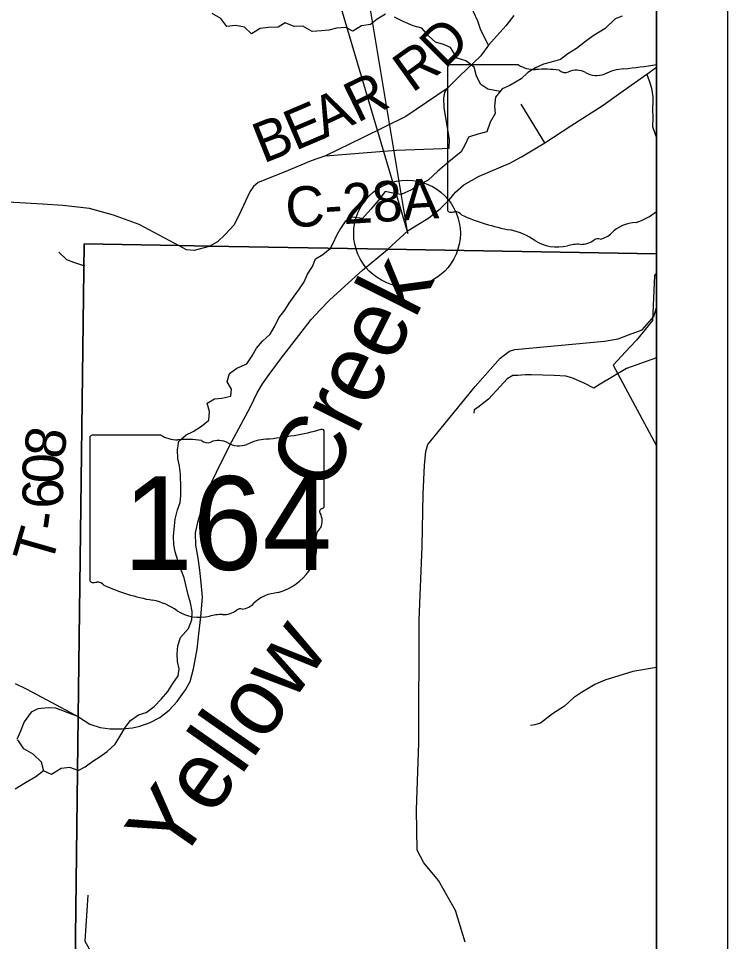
# Model space of a CAD drawing. Extents: x -20.5 to 34, y -66 to 23.9.
# Drawn here: x 8.003 to 9, y 16.344 to 17.643 of the extents above; entities that cross this region are included whole.
import ezdxf

# ---------------------------------------------------------------- set-up
doc = ezdxf.new("R2010")
doc.units = 0
for name, color, linetype in [('Default', 7, 'Continuous'), ('GM_X_County_Road_Text', 7, 'Continuous'), ('GM_X_County_Text', 7, 'Continuous'), ('GM_X_Minor_River_Text', 7, 'Continuous'), ('GM_X_Section_Text', 7, 'Continuous'), ('GM_X_State_Route', 7, 'Continuous'), ('GM_X_State_Shield', 7, 'Continuous'), ('GM_X_Township_Road', 7, 'Continuous'), ('GM_X_Township_Road_Text', 7, 'Continuous'), ('GM_X_Unincorporated', 7, 'Continuous'), ('GM_X_Unincorporated_Location', 7, 'Continuous'), ('SH_Cut_Line', 7, 'Continuous'), ('SH_Data', 7, 'Continuous'), ('SH_Text', 7, 'Continuous')]:
    doc.layers.add(name, color=color, linetype=linetype)

msp = doc.modelspace()

# ---------------------------------------------------------------- linework, layer by layer
at = {"layer": 'Default'}
for points in [[(2.1, 20.9), (8.9, 20.9), (8.9, 14.1), (2.1, 14.1)], [(8.9, 14.3068), (8.9, 17.3115), (8.5216, 17.3182), (8.271, 17.3227), (8.2289, 17.3235), (8.0955, 17.3258), (8.087, 16.6605), (8.0825, 16.3121), (8.0784, 15.8902), (8.0662, 14.9881), (8.0605, 14.6038), (8.0589, 14.5033), (8.0585, 14.4588), (8.0565, 14.3169), (8.8167, 14.3089)], [(8.9, 17.0415), (8.9, 17.285), (8.8972, 17.2813), (8.8943, 17.2178), (8.8719, 17.1901), (8.8625, 17.1804), (8.8391, 17.1549)]]:
    msp.add_lwpolyline(points, close=True, dxfattribs=at)
msp.add_lwpolyline([(8.0662, 14.9881), (8.0784, 15.8902), (8.0825, 16.3121), (8.087, 16.6605), (8.0955, 17.3258), (8.2289, 17.3235), (8.271, 17.3227), (8.5216, 17.3182), (8.9, 17.3115), (8.9, 18.8361), (8.7292, 18.8379), (8.3774, 18.8452)], dxfattribs=at)
at = {"layer": 'GM_X_County_Text'}
msp.add_line((8.7431, 17.4678), (8.7098, 17.5223), dxfattribs=at)
for points in [[(8.664, 17.6053), (8.6581, 17.616), (8.6526, 17.6277), (8.6487, 17.6393), (8.6426, 17.6523), (8.6394, 17.6621), (8.6374, 17.6671), (8.6406, 17.671)], [(8.8865, 17.5646), (8.8911, 17.5508), (8.8931, 17.5448), (8.8942, 17.5388), (8.8948, 17.5333), (8.895, 17.5252), (8.8943, 17.5162), (8.895, 17.5027), (8.8945, 17.4909), (8.8985, 17.4785), (8.9, 17.4753)], [(8.6086, 17.4603), (8.6091, 17.4726), (8.6014, 17.5172), (8.6012, 17.5308), (8.6026, 17.5386), (8.6056, 17.5444)]]:
    msp.add_lwpolyline(points, dxfattribs=at)
at = {"layer": 'GM_X_Minor_River_Text'}
for points in [[(8.5191, 17.649), (8.5075, 17.642), (8.4978, 17.6343), (8.4853, 17.6326), (8.473, 17.6252), (8.4634, 17.6304), (8.4502, 17.6294), (8.4393, 17.6266), (8.4291, 17.6257), (8.4158, 17.6247), (8.4028, 17.6321), (8.3907, 17.6316), (8.3778, 17.6367), (8.3681, 17.6308), (8.3544, 17.6303), (8.3427, 17.6286), (8.3304, 17.6212), (8.3208, 17.6305), (8.3082, 17.633), (8.2958, 17.6317), (8.2876, 17.6429), (8.2754, 17.6499)], [(8.8518, 17.646), (8.842, 17.6425), (8.8279, 17.6286), (8.811, 17.6185), (8.8001, 17.6104), (8.7874, 17.6007), (8.7754, 17.5933), (8.7653, 17.5852), (8.7518, 17.5816), (8.7412, 17.5784), (8.7299, 17.5737), (8.7194, 17.5667), (8.7097, 17.5582), (8.694, 17.5488), (8.6831, 17.5438), (8.6738, 17.5322), (8.6725, 17.5193), (8.6734, 17.5091), (8.6664, 17.4968), (8.6617, 17.4835), (8.6489, 17.4803), (8.6357, 17.4759), (8.6309, 17.4656), (8.6254, 17.4553), (8.6082, 17.441), (8.5925, 17.4282), (8.5791, 17.4155), (8.5656, 17.4085), (8.5558, 17.4019), (8.5412, 17.3952), (8.5317, 17.3966), (8.5188, 17.3994), (8.5095, 17.3879), (8.4983, 17.3745), (8.4868, 17.3614), (8.472, 17.3631), (8.4623, 17.3572), (8.456, 17.3473), (8.4501, 17.3373), (8.445, 17.3262), (8.4412, 17.3194)], [(8.6803, 17.5403), (8.663, 17.5435), (8.6531, 17.5501), (8.6472, 17.5618), (8.6436, 17.5746), (8.6321, 17.5832), (8.6196, 17.5872), (8.6103, 17.6022), (8.6004, 17.6062), (8.5894, 17.6095), (8.5794, 17.6184), (8.5701, 17.6293), (8.558, 17.6325), (8.5439, 17.6388), (8.5317, 17.645)], [(8.0871, 16.5848), (8.0968, 16.5899), (8.1077, 16.5978), (8.1178, 16.6042), (8.1275, 16.6113), (8.1387, 16.6215), (8.1456, 16.6323), (8.1528, 16.6451), (8.1606, 16.6552), (8.1718, 16.6632), (8.1823, 16.6661), (8.1939, 16.6748), (8.2043, 16.6854), (8.2131, 16.6959), (8.22, 16.7072), (8.2273, 16.718), (8.2289, 16.7276), (8.2267, 16.7382), (8.226, 16.7488), (8.2272, 16.7603), (8.2307, 16.7718), (8.2422, 16.7843), (8.2468, 16.7966), (8.2472, 16.8084), (8.2449, 16.8205), (8.2416, 16.8318), (8.2359, 16.856), (8.231, 16.8692), (8.2273, 16.8789), (8.2234, 16.8925), (8.2213, 16.9024), (8.2209, 16.9145), (8.2218, 16.9241), (8.2233, 16.9382), (8.2267, 16.9516), (8.2302, 16.9616), (8.2311, 16.9715), (8.2312, 16.9818), (8.2306, 17.0015), (8.2295, 17.0129), (8.2269, 17.0235), (8.2266, 17.036), (8.2285, 17.0482), (8.2389, 17.0569), (8.2487, 17.0618), (8.2603, 17.0693), (8.2707, 17.0776), (8.2715, 17.0898), (8.2685, 17.1015), (8.2786, 17.1079), (8.2888, 17.1086), (8.3017, 17.1116), (8.3026, 17.1215), (8.2962, 17.1316), (8.2996, 17.1435), (8.3101, 17.151), (8.324, 17.1568), (8.3317, 17.1684), (8.3378, 17.1792), (8.3463, 17.189), (8.3571, 17.1988), (8.3636, 17.2097), (8.369, 17.2216), (8.3775, 17.2325), (8.3836, 17.2422), (8.3906, 17.2523), (8.3979, 17.2624), (8.4049, 17.2725), (8.4095, 17.2829), (8.4164, 17.2941), (8.4207, 17.3045), (8.4309, 17.3107), (8.4412, 17.3194)], [(8.0962, 17.2944), (8.081, 17.2996), (8.0711, 17.3032), (8.0599, 17.314)], [(8.9, 17.1656), (8.8581, 17.1502), (8.8209, 17.1281), (8.8119, 17.1226), (8.7985, 17.1299), (8.7809, 17.1371), (8.7728, 17.1396), (8.7561, 17.1404), (8.7242, 17.1416), (8.7158, 17.1414), (8.7102, 17.1409), (8.7052, 17.1404), (8.698, 17.1403), (8.6901, 17.1359), (8.6805, 17.1251), (8.6637, 17.1073), (8.6491, 17.0956), (8.6439, 17.0924), (8.6432, 17.0875)], [(8.9, 16.7294), (8.8668, 16.7238), (8.8276, 16.7119), (8.8133, 16.7056), (8.7945, 16.6942), (8.7833, 16.6867), (8.7706, 16.675), (8.7541, 16.6644), (8.7372, 16.6512), (8.7289, 16.6487), (8.7229, 16.6482)], [(8.0386, 16.5839), (8.0352, 16.5962), (8.0237, 16.6078), (8.0107, 16.6152), (8.0022, 16.6276)], [(8.0871, 16.5848), (8.0751, 16.5889), (8.063, 16.5876), (8.0495, 16.579), (8.0381, 16.5841), (8.0272, 16.5756), (8.013, 16.5675), (7.9983, 16.5585)], [(8.1003, 16.409), (8.0961, 16.3444), (8.1036, 16.3313)]]:
    msp.add_lwpolyline(points, dxfattribs=at)
at = {"layer": 'GM_X_State_Route'}
msp.add_line((8.5987, 17.4601), (8.6086, 17.4603), dxfattribs=at)
for points in [[(8.6994, 17.6472), (8.6882, 17.6326), (8.664, 17.6053), (8.6531, 17.5904), (8.6231, 17.5619), (8.6056, 17.5444), (8.5477, 17.5051), (8.4866, 17.4748), (8.4345, 17.4496), (8.4147, 17.4424), (8.3764, 17.4266), (8.3399, 17.4123), (8.3334, 17.4065), (8.3285, 17.399), (8.3163, 17.3729), (8.3062, 17.3524), (8.2937, 17.3388), (8.2829, 17.3288), (8.2712, 17.3222), (8.25, 17.3162), (8.2392, 17.3173), (8.2291, 17.323), (8.1728, 17.3531), (8.1366, 17.3663), (8.1026, 17.3757), (8.0654, 17.3799), (8.0367, 17.3815), (8.0049, 17.3833), (7.9794, 17.3849)], [(8.4345, 17.4496), (8.5344, 17.4574), (8.5987, 17.4601)], [(8.6311, 16.3432), (8.6177, 16.3874), (8.5934, 16.4298), (8.5728, 16.4548), (8.5637, 16.4725), (8.5626, 16.5291), (8.566, 16.6237), (8.5664, 16.7968), (8.5707, 16.8998), (8.5719, 16.9742), (8.5741, 17.0137), (8.5756, 17.0335), (8.5784, 17.0434), (8.645, 17.1252), (8.6805, 17.165), (8.6932, 17.1748), (8.7011, 17.1772), (8.827, 17.1888), (8.8463, 17.1922), (8.8609, 17.1978), (8.8798, 17.2048), (8.8964, 17.2235), (8.9, 17.2362)], [(8.0872, 16.66), (8.0554, 16.6725), (8.0446, 16.6726), (8.0303, 16.6712), (8.0206, 16.6669), (8.011, 16.653), (8.006, 16.64), (8.0007, 16.6282)]]:
    msp.add_lwpolyline(points, dxfattribs=at)
at = {"layer": 'GM_X_State_Shield'}
for p, q in [((8.7062, 17.5775), (8.6096, 17.5775)), ((8.9, 17.3712), (8.9, 17.5784)), ((8.6064, 17.574), (8.6064, 17.3739))]:
    msp.add_line(p, q, dxfattribs=at)
for centre, major_axis, start_param, end_param in [((8.6102, 17.5745), (0.00382, 0), 1.727492, 3.291633), ((8.7291, 17.6007), (0.037, 0), 4.042888, 4.731792), ((8.8186, 17.8503), (0.3495, 0), 4.814394, 4.947512), ((8.7414, 17.4651), (0.133, 0), 1.404758, 1.657859), ((8.7716, 17.5755), (0.0107, 0), 3.836095, 5.185415), ((8.7873, 17.5524), (0.0222, 0), 0.950623, 2.079405), ((8.816, 17.5841), (0.0267, 0), 4.08156, 5.145723), ((8.8632, 17.5164), (0.0703, 0), 1.699012, 2.107814), ((8.6102, 17.3735), (0.00385, 0), 2.993084, 4.5083), ((8.6108, 17.394), (0.0294, 0), 4.665946, 4.897461), ((8.6168, 17.3624), (0.0106, 0), 0.519207, 1.627899), ((8.8382, 17.4206), (0.0874, 0), 5.101753, 5.498241), ((8.7506, 17.5422), (0.2524, 0), 4.195997, 4.488961), ((8.875, 17.3177), (0.0479, 0), 1.647645, 2.488434), ((8.6754, 17.284), (0.079, 0), 0.823519, 1.323587), ((8.7608, 17.3614), (0.0501, 0), 4.026481, 4.996735), ((8.7934, 17.3464), (0.0267, 0), 4.691044, 5.507374), ((8.8176, 17.327), (0.00752, 0), 1.147584, 2.315152), ((8.8144, 17.3545), (0.0282, 0), 4.937069, 5.64225), ((8.7897, 17.2922), (0.0412, 0), 1.495662, 1.94098)]:
    msp.add_ellipse(centre, major_axis=major_axis, ratio=0.8, start_param=start_param, end_param=end_param, dxfattribs=at)
at = {"layer": 'GM_X_Township_Road'}
for points in [[(8.5218, 17.3176), (8.5511, 17.3444), (8.5801, 17.3626), (8.5961, 17.3752), (8.6089, 17.3883), (8.6176, 17.3986), (8.6294, 17.409), (8.6508, 17.4211), (8.6939, 17.4391), (8.7103, 17.4481), (8.7431, 17.4678), (8.7797, 17.4917), (8.8251, 17.521), (8.8466, 17.5362), (8.8645, 17.5489), (8.8865, 17.5646), (8.9, 17.5742)], [(8.2568, 16.777), (8.2596, 16.8007), (8.2615, 16.8284), (8.26, 16.8489), (8.2582, 16.8667), (8.2557, 16.8834), (8.2524, 16.9019), (8.2518, 16.9186), (8.255, 16.9342), (8.2633, 16.9609), (8.275, 16.9907), (8.2879, 17.0182), (8.303, 17.0476), (8.3196, 17.0779), (8.3292, 17.0966), (8.3384, 17.1161), (8.3462, 17.1287), (8.3555, 17.1421), (8.373, 17.1652), (8.3972, 17.197), (8.4147, 17.2193), (8.4274, 17.2327), (8.4405, 17.2466), (8.4618, 17.2662), (8.4869, 17.2886), (8.5218, 17.3176)], [(8.0872, 16.66), (8.1032, 16.65), (8.1177, 16.6453), (8.1318, 16.6432), (8.1485, 16.6431), (8.1632, 16.6448), (8.1738, 16.6468), (8.1882, 16.652), (8.2017, 16.6594), (8.2148, 16.6694), (8.226, 16.6817), (8.2379, 16.6982), (8.2442, 16.7097), (8.2493, 16.7276), (8.2542, 16.7554), (8.2568, 16.777)], [(7.9984, 16.7071), (8.0139, 16.6994), (8.0498, 16.6802), (8.0872, 16.66)]]:
    msp.add_lwpolyline(points, dxfattribs=at)
at = {"layer": 'GM_X_Unincorporated'}
for p, q in [((8.2031, 17.0564), (8.1066, 17.0564)), ((8.4329, 16.9567), (8.4329, 17.0614)), ((8.1034, 17.053), (8.1034, 16.8529)), ((8.4329, 16.9567), (8.4329, 16.9567))]:
    msp.add_line(p, q, dxfattribs=at)
for centre, major_axis, start_param, end_param in [((8.1071, 17.0534), (0.00382, 0), 1.712693, 3.28349), ((8.2261, 17.0797), (0.037, 0), 4.042523, 4.731795), ((8.3155, 17.3293), (0.3495, 0), 4.814394, 5.042369), ((8.4293, 17.0618), (0.00367, 0), 6.141152, 7.989035), ((8.2384, 16.9441), (0.133, 0), 1.404758, 1.657858), ((8.2686, 17.0544), (0.0107, 0), 3.836095, 5.185415), ((8.2843, 17.0313), (0.0222, 0), 0.950623, 2.079405), ((8.3129, 17.063), (0.0267, 0), 4.081561, 5.145723), ((8.3601, 16.9953), (0.0703, 0), 1.699011, 2.107814), ((8.4321, 16.949), (0.00568, 0), 1.883978, 3.671073), ((8.429, 16.9563), (0.00393, 0), 5.05454, 6.418171), ((8.396, 16.9358), (0.0341, 0), 5.934695, 6.695948), ((8.4461, 16.9129), (0.0248, 0), 2.387724, 3.262537), ((8.3351, 16.8996), (0.0874, 0), 5.101752, 6.440018), ((8.1072, 16.8524), (0.00385, 0), 3.00124, 4.508301), ((8.1078, 16.8729), (0.0294, 0), 4.665946, 4.897461), ((8.1138, 16.8413), (0.0106, 0), 0.519207, 1.627899), ((8.2476, 17.0211), (0.2524, 0), 4.195997, 4.488961), ((8.1723, 16.763), (0.079, 0), 0.823519, 1.323587), ((8.372, 16.7967), (0.0479, 0), 1.647645, 2.488434), ((8.2578, 16.8403), (0.0501, 0), 4.026481, 4.996735), ((8.2904, 16.8253), (0.0267, 0), 4.691044, 5.507374), ((8.3145, 16.806), (0.00752, 0), 1.147584, 2.315152), ((8.3113, 16.8335), (0.0282, 0), 4.937069, 5.64225), ((8.2867, 16.7711), (0.0412, 0), 1.495662, 1.94098)]:
    msp.add_ellipse(centre, major_axis=major_axis, ratio=0.8, start_param=start_param, end_param=end_param, dxfattribs=at)
at = {"layer": 'SH_Cut_Line'}
msp.add_lwpolyline([(8.0662, 14.9881), (8.0784, 15.8902), (8.0825, 16.3121), (8.087, 16.6605), (8.0955, 17.3258), (8.2289, 17.3235), (8.271, 17.3227), (8.5216, 17.3182), (8.9, 17.3115), (8.9, 20.9), (2.1, 20.9), (2.1, 14.4131)], dxfattribs=at)
msp.add_lwpolyline([(8.9, 14.3068), (8.9, 17.3115), (8.5216, 17.3182), (8.271, 17.3227), (8.2289, 17.3235), (8.0955, 17.3258), (8.087, 16.6605), (8.0825, 16.3121), (8.0784, 15.8902), (8.0662, 14.9881), (8.0605, 14.6038), (8.0589, 14.5033), (8.0585, 14.4588), (8.0565, 14.3169), (8.8167, 14.3089)], close=True, dxfattribs=at)
at = {"layer": 'SH_Data'}
for p, q in [((9, 21), (9, 14)), ((8.9, 20.9), (8.9, 14.1))]:
    msp.add_line(p, q, dxfattribs=at)
at = {"layer": 'SH_Text'}
msp.add_lwpolyline([(8.5505, 17.3404), (8.3774, 18.3792), (8.2428, 18.3792)], close=True, dxfattribs=at)
msp.add_circle((8.5493, 17.3404), 0.075, dxfattribs=at)

# ---------------------------------------------------------------- texts
at = {"layer": 'GM_X_County_Road_Text'}
for s, height, rotation, p in [('Creek', 0.09469, 63.2958, (8.4368, 16.9733)), ('Yellow', 0.09471, 54.983, (8.2266, 16.4491))]:
    msp.add_text(s, height=height, rotation=rotation, dxfattribs=at).set_placement(p)
at = {"layer": 'GM_X_Section_Text'}
for s, rotation, p in [('8', 80.8384, (8.0658, 17.0212)), ('0', 88.5635, (8.0651, 16.9882)), ('6', 91.7241, (8.0662, 16.9541)), ('-', 82.1938, (8.0625, 16.9207)), ('T', 73.9781, (8.0489, 16.8711))]:
    msp.add_text(s, height=0.0568, rotation=rotation, dxfattribs=at).set_placement(p)
at = {"layer": 'GM_X_Township_Road_Text'}
for s, height, rotation, p in [('D', 0.0568, 44.8007, (8.6019, 17.5709)), ('R', 0.0568, 35.6146, (8.5565, 17.5374)), ('R', 0.0568, 25.9888, (8.4792, 17.4956)), ('A', 0.0568, 25.2482, (8.4332, 17.474)), ('E', 0.0568, 23.0721, (8.392, 17.4563)), ('B', 0.0568, 21.6666, (8.3472, 17.4385)), ('C-28A', 0.05682, 3.6367, (8.3801, 17.3483))]:
    msp.add_text(s, height=height, rotation=rotation, dxfattribs=at).set_placement(p)
at = {"layer": 'GM_X_Unincorporated'}
msp.add_text('164', height=0.13184, dxfattribs=at).set_placement((8.1499, 16.867))
at = {"layer": 'GM_X_Unincorporated_Location'}
for s, p in [('s', (8.7675, 17.4607)), ('r', (8.7675, 17.4607)), ('s', (8.2645, 16.9396)), ('r', (8.2644, 16.9396))]:
    msp.add_text(s, height=0.000189, dxfattribs=at).set_placement(p)
for p in [(8.7006, 17.4469), (8.1976, 16.9258)]:
    msp.add_text('164', height=0.000189, rotation=0, dxfattribs=at).set_placement(p)

doc.saveas('drawing.dxf')
